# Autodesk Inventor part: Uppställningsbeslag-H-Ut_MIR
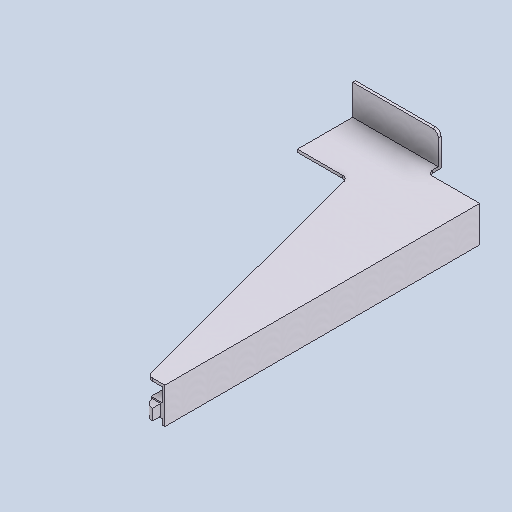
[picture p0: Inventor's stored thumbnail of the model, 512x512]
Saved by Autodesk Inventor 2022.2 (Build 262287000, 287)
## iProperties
Created: 2019-06
Part Number: Uppställningsbeslag-H-Ut_MIR
Material: Aluminum 6061, Welded
Document SubType Name: Modeling
Designer: cl
Density: 2.7 g/cm^3
Appearance: Weld - Aluminum
Author: cl
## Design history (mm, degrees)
derived "Uppställningsbeslag-H-Ut.ipt"
  sketch "Sketch1"
    geometry: L1 (-95, 25)-(-250, 25) reference; L2 (-250, 25)-(-250, -80) reference; L3 (-250, -80)-(-167.693, -80) reference; L4 (0, 0)-(0, -570) reference; L5 (0, -570)-(-22.307, -570) reference; L6 (-31.973, -562.564)-(-158.027, -87.436) reference; L7 (-95, 25)-(-95, 10) reference; L8 (-85, 0)-(0, 0) reference; A1 r 10 centre (-167.693, -90) between (-158.027, -87.436) and (-167.693, -80) reference; A2 r 10 centre (-22.307, -560) between (-31.973, -562.564) and (-22.307, -570) reference; A3 r 10 centre (-85, 10) between (-95, 10) and (-85, 0) reference; 4 further points
  sketch "Sketch2"
    geometry: L1 (250, -25)-(95, -25) reference; L2 (95, -25)-(95, -20) reference; L3 (95, -20)-(250, -20) reference; L4 (250, -20)-(250, -25) reference; L5 (250, -25)-(95, -25) reference; L6 (250, 80)-(250, -25) reference; L7 (95, -25)-(95, -10) reference; 1 further point
  sketch "Sketch3"
    geometry: L1 (0, 0)-(5, 0) reference; L2 (5, 0)-(5, -570) reference; L3 (5, -570)-(0, -570) reference; L4 (0, -570)-(0, 0) reference; L5 (0, 0)-(0, -570) reference; L6 (0, -570)-(22.307, -570) reference; L7 (85, 0)-(0, 0) reference
  sketch "Sketch4"
    geometry: L1 (-5, -5)-(-5, -65) reference; L2 (-5, -30)-(-25, -30) reference; L3 (-25, -30)-(-25, -55) reference; L4 (-25, -55)-(-5, -55) reference; L5 (-5, -55)-(-5, -30) reference; L6 (-5, -5)-(-22.307, -5) reference; 1 further point
  sketch "Sketch5"
    geometry: L1 (-22.5, -32.5)-(-7.5, -32.5) reference; L2 (-7.5, -32.5)-(-7.5, -52.5) reference; L3 (-7.5, -52.5)-(-22.5, -52.5) reference; L4 (-22.5, -52.5)-(-22.5, -32.5) reference; L5 (-25, -30)-(-5, -30) reference; L6 (-25, -55)-(-25, -30) reference; 1 further point
feature "Solid1::Uppställningsbeslag-H-Ut.ipt"
tag "TaggingFeature1"
body "Solid1"
